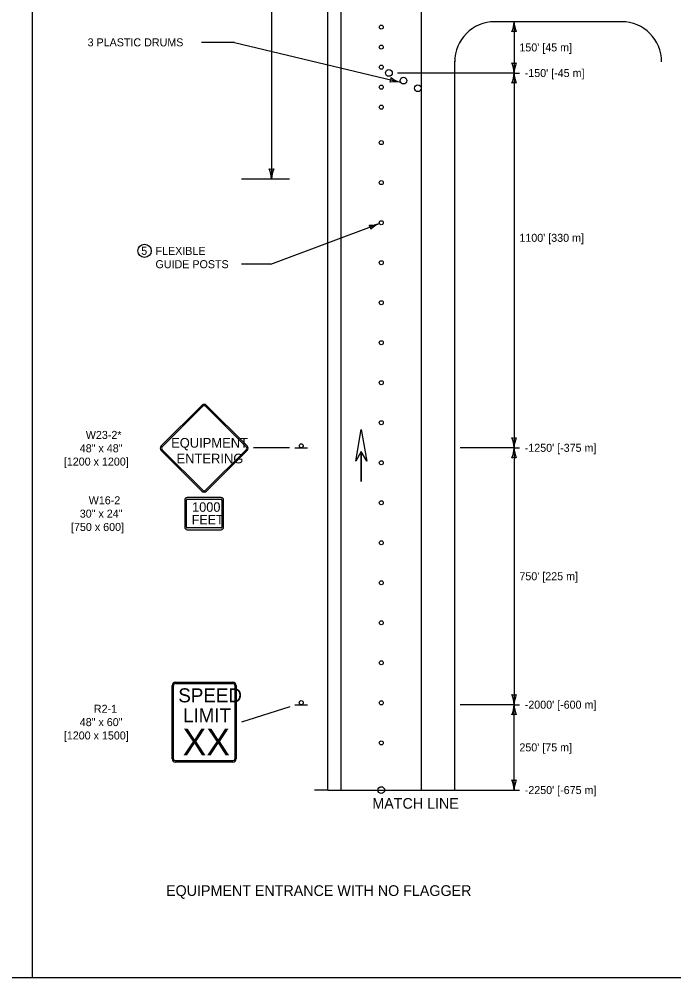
# Model space of a CAD drawing. Extents: x 49991.4 to 50021, y 49987.6 to 50011.4.
# Drawn here: x 50004.19 to 50009.09, y 49987.8 to 49994.99 of the extents above; entities that cross this region are included whole.
import ezdxf

# ---------------------------------------------------------------- set-up
doc = ezdxf.new("R2010")
doc.units = 0
for name, color, linetype in [('Level 1', 7, 'Continuous'), ('Level 2', 7, 'Continuous'), ('Level 3', 7, 'Continuous'), ('Level 6', 7, 'Continuous')]:
    doc.layers.add(name, color=color, linetype=linetype)

msp = doc.modelspace()

# ---------------------------------------------------------------- linework, layer by layer
at = {"layer": 'Level 1'}
for p, q in [((50006.5002, 49989.2066), (50006.5002, 49998.1941)), ((50006.6002, 49989.2066), (50006.6002, 49998.1941)), ((50007.2002, 49989.2066), (50007.2002, 49998.1941)), ((50008.7008, 49994.9668), (50007.7502, 49994.9668)), ((50007.4502, 49989.2066), (50007.4502, 49994.6713)), ((50005.251, 49991.787), (50005.5551, 49992.091)), ((50005.2581, 49991.7799), (50005.5621, 49992.084)), ((50005.5834, 49992.084), (50005.8874, 49991.7799)), ((50005.5904, 49992.091), (50005.8945, 49991.787)), ((50005.5621, 49991.4546), (50005.2581, 49991.7587)), ((50005.8874, 49991.7587), (50005.5834, 49991.4546)), ((50006.2519, 49991.7726), (50006.3479, 49991.7726)), ((50005.5551, 49991.4476), (50005.251, 49991.7516)), ((50005.8945, 49991.7516), (50005.5904, 49991.4476)), ((50006.7502, 49991.5199), (50006.7502, 49991.7458)), ((50006.7505, 49991.5199), (50006.7505, 49991.7458)), ((50005.7001, 49991.4002), (50005.4453, 49991.4002)), ((50005.4271, 49991.38), (50005.4271, 49991.1784)), ((50005.4393, 49991.1784), (50005.4393, 49991.38)), ((50005.4453, 49991.3868), (50005.7001, 49991.3868)), ((50005.7061, 49991.38), (50005.7061, 49991.1784)), ((50005.7183, 49991.1784), (50005.7183, 49991.38)), ((50005.7001, 49991.1717), (50005.4453, 49991.1717)), ((50005.4453, 49991.1583), (50005.7001, 49991.1583)), ((50005.3327, 49989.4409), (50005.3327, 49989.9909)), ((50005.3427, 49989.4409), (50005.3427, 49989.9909)), ((50005.3577, 49990.0159), (50005.7877, 49990.0159)), ((50005.3577, 49990.0059), (50005.7877, 49990.0059)), ((50005.8027, 49989.9909), (50005.8027, 49989.4409)), ((50005.8127, 49989.9909), (50005.8127, 49989.4409)), ((50006.252, 49989.8466), (50006.348, 49989.8466)), ((50005.7877, 49989.4259), (50005.3577, 49989.4259)), ((50005.7877, 49989.4159), (50005.3577, 49989.4159))]:
    msp.add_line(p, q, dxfattribs=at)
for points in [[(49999.3835, 49998.9992), (50016.7501, 49998.9992), (50016.7501, 49987.7988), (49999.3835, 49987.7988)], [(50006.7085, 49991.6735), (50006.7502, 49991.91), (50006.7921, 49991.6735), (50006.7502, 49991.7457)]]:
    msp.add_lwpolyline(points, close=True, dxfattribs=at)
for centre, radius in [((50006.9002, 49994.9266), 0.015), ((50006.9002, 49994.7766), 0.015), ((50006.9002, 49994.6266), 0.015), ((50006.9575, 49994.583), 0.025), ((50006.9002, 49994.4766), 0.015), ((50007.0658, 49994.5256), 0.025), ((50007.174, 49994.4683), 0.025), ((50006.9002, 49994.3266), 0.015), ((50006.9002, 49994.3266), 0.015), ((50006.9002, 49994.0606), 0.015), ((50006.9002, 49993.7606), 0.015), ((50006.9002, 49993.4606), 0.015), ((50006.9002, 49993.1606), 0.015), ((50006.9002, 49992.8606), 0.015), ((50006.9002, 49992.5606), 0.015), ((50006.9002, 49992.2606), 0.015), ((50006.9002, 49991.9606), 0.015), ((50006.2999, 49991.7878), 0.0152), ((50006.9002, 49991.6606), 0.015), ((50006.9002, 49991.3606), 0.015), ((50006.9002, 49991.0606), 0.015), ((50006.9002, 49990.7606), 0.015), ((50006.9002, 49990.4606), 0.015), ((50006.9002, 49990.1606), 0.015), ((50006.9002, 49990.1606), 0.015), ((50006.3, 49989.8618), 0.0152), ((50006.9002, 49989.8606), 0.015), ((50006.9002, 49989.5606), 0.015), ((50006.9001, 49989.2066), 0.025)]:
    msp.add_circle(centre, radius, dxfattribs=at)
for centre, radius, start, end in [((50007.7502, 49994.6668), 0.3, 90, 180), ((50008.7008, 49994.6668), 0.3, 0, 90), ((50005.5727, 49992.0733), 0.025, 45, 135), ((50005.5727, 49992.0733), 0.015, 45, 135), ((50005.2686, 49991.7693), 0.025, 134.99976, 225), ((50005.2686, 49991.7693), 0.015, 134.99976, 225), ((50005.8768, 49991.7693), 0.015, 315, 45), ((50005.8768, 49991.7693), 0.025, 315, 45), ((50005.5727, 49991.4652), 0.025, 225.00043, 315), ((50005.5727, 49991.4652), 0.015, 225.00043, 315), ((50005.3577, 49989.991), 0.025, 90, 180), ((50005.3577, 49989.991), 0.015, 90, 180), ((50005.7877, 49989.991), 0.025, 0, 90), ((50005.7877, 49989.991), 0.015, 0, 90), ((50005.3577, 49989.441), 0.025, 180, 270), ((50005.3577, 49989.441), 0.015, 180, 270), ((50005.7877, 49989.441), 0.025, 270, 0), ((50005.7877, 49989.441), 0.015, 270, 0)]:
    msp.add_arc(centre, radius, start, end, dxfattribs=at)
for centre, major_axis, start_param, end_param in [((50005.4453, 49991.38), (0, 0.0202), 0, 1.570796), ((50005.7001, 49991.38), (0, 0.0202), 4.712389, 6.283185), ((50005.4453, 49991.38), (0, 0.00672), 0, 1.570796), ((50005.7001, 49991.38), (0, 0.00672), 4.712389, 6.283185), ((50005.4453, 49991.1784), (0, -0.0202), 4.712389, 6.283185), ((50005.4453, 49991.1784), (0, -0.00672), 4.712389, 6.283185), ((50005.7001, 49991.1784), (0, -0.00672), 0, 1.570796), ((50005.7001, 49991.1784), (0, -0.0202), 0, 1.570796)]:
    msp.add_ellipse(centre, major_axis=major_axis, ratio=0.9025, start_param=start_param, end_param=end_param, dxfattribs=at)
at = {"layer": 'Level 2'}
msp.add_circle((50005.126, 49993.2496), 0.05, dxfattribs=at)
at = {"layer": 'Level 3'}
for p, q in [((50004.2835, 49998.9992), (50004.2835, 49987.7988)), ((50006.0772, 49996.2068), (50006.0772, 49993.7873)), ((50007.895, 49994.9668), (50007.895, 49994.5826)), ((50005.8, 49994.8126), (50005.553, 49994.8126)), ((50005.8, 49994.8126), (50007.0437, 49994.5138)), ((50007.895, 49994.5826), (50007.0225, 49994.5826)), ((50007.895, 49994.5826), (50007.935, 49994.5826)), ((50007.895, 49994.5826), (50007.895, 49993.7873)), ((50006.212, 49993.7873), (50005.8527, 49993.7873)), ((50007.895, 49993.7873), (50007.895, 49991.7726)), ((50006.0733, 49993.1494), (50006.8864, 49993.4548)), ((50006.0733, 49993.1494), (50005.8527, 49993.1494)), ((50006.2119, 49991.7726), (50005.9418, 49991.7726)), ((50007.895, 49991.7726), (50007.4902, 49991.7726)), ((50007.895, 49991.7726), (50007.935, 49991.7726)), ((50007.895, 49991.7726), (50007.895, 49989.8466)), ((50006.215, 49989.8314), (50005.8527, 49989.7159)), ((50007.895, 49989.8466), (50007.4902, 49989.8466)), ((50007.895, 49989.2066), (50007.895, 49989.8466)), ((50007.895, 49989.8466), (50007.935, 49989.8466))]:
    msp.add_line(p, q, dxfattribs=at)
for centre, radius, start, end in [((50007.6728, 49994.976), 0.2223, 337.45601, 357.63952), ((50008.1277, 49994.9783), 0.233, 182.82731, 202.07716), ((50007.895, 49994.8386), 0.0548, 72.13882, 107.86118), ((50007.895, 49994.7108), 0.0548, 252.13882, 287.86118), ((50007.6623, 49994.5711), 0.233, 2.82731, 22.07716), ((50008.1171, 49994.5734), 0.2223, 157.45601, 177.63952), ((50007.6623, 49994.5941), 0.233, 337.92284, 357.17269), ((50008.1171, 49994.5917), 0.2223, 182.36048, 202.54399), ((50006.9191, 49994.5438), 0.0548, 328.62967, 4.35204), ((50007.0005, 49994.2848), 0.233, 79.31817, 98.56802), ((50007.1045, 49994.7277), 0.2223, 233.94687, 254.13037), ((50007.895, 49994.4544), 0.0548, 72.13882, 107.86118), ((50006.0772, 49993.9155), 0.0548, 252.13882, 287.86118), ((50005.8445, 49993.7758), 0.233, 2.82731, 22.07716), ((50006.2993, 49993.7781), 0.2223, 157.45601, 177.63952), ((50006.813, 49993.6647), 0.2223, 269.09342, 289.27693), ((50006.7672, 49993.4076), 0.0548, 3.77623, 39.49859), ((50006.9829, 49993.2428), 0.233, 114.46472, 133.71457), ((50007.6728, 49991.7634), 0.2223, 2.36048, 22.54399), ((50007.895, 49991.9008), 0.0548, 252.13882, 287.86118), ((50008.1277, 49991.7611), 0.233, 157.92284, 177.17269), ((50007.6728, 49991.7817), 0.2223, 337.45601, 357.63952), ((50008.1277, 49991.7841), 0.233, 182.82731, 202.07716), ((50007.895, 49991.6444), 0.0548, 72.13882, 107.86118), ((50007.895, 49989.9748), 0.0548, 252.13882, 287.86118), ((50007.6623, 49989.8351), 0.233, 2.82731, 22.07716), ((50008.1171, 49989.8374), 0.2223, 157.45601, 177.63952), ((50007.6728, 49989.8557), 0.2223, 337.45601, 357.63952), ((50008.1277, 49989.8581), 0.233, 182.82731, 202.07716), ((50007.895, 49989.7184), 0.0548, 72.13882, 107.86118), ((50007.895, 49989.3348), 0.0548, 252.13882, 287.86118), ((50007.6623, 49989.1951), 0.233, 2.82731, 22.07716), ((50008.1171, 49989.1974), 0.2223, 157.45601, 177.63952)]:
    msp.add_arc(centre, radius, start, end, dxfattribs=at)
at = {"layer": 'Level 6'}
for p, q in [((50006.5002, 49989.2066), (50006.4002, 49989.2066)), ((50006.5002, 49989.2066), (50007.895, 49989.2066)), ((50007.895, 49989.2066), (50007.935, 49989.2066))]:
    msp.add_line(p, q, dxfattribs=at)

# ---------------------------------------------------------------- texts
at = {"layer": 'Level 1'}
for s, height, p in [('EQUIPMENT', 0.0725, (50005.3249, 49991.7735)), ('ENTERING', 0.0725, (50005.3656, 49991.656)), ('1000', 0.07124, (50005.4824, 49991.2927)), ('FEET', 0.06989, (50005.4795, 49991.1986)), ('SPEED', 0.10512, (50005.3789, 49989.8643)), ('LIMIT', 0.10512, (50005.4143, 49989.7142)), ('XX', 0.19892, (50005.4111, 49989.4669))]:
    msp.add_text(s, height=height, dxfattribs=at).set_placement(p)
at = {"layer": 'Level 2'}
for s, height, p in [('3 PLASTIC DRUMS', 0.06, (50004.6992, 49994.7826)), ("150' [45 m]", 0.06, (50007.935, 49994.7446)), ("-150' [-45 m]", 0.06, (50007.975, 49994.5526)), ("1100' [330 m]", 0.06, (50007.935, 49993.3171)), ('5', 0.06, (50005.1011, 49993.2196)), ('FLEXIBLE', 0.06, (50005.2081, 49993.2194)), ('GUIDE POSTS', 0.06, (50005.2081, 49993.1194)), ('W23-2*', 0.06, (50004.6857, 49991.8393)), ('48" x 48"', 0.06, (50004.6405, 49991.7393)), ("-1250' [-375 m]", 0.06, (50007.975, 49991.7426)), ('[1200 x 1200]', 0.06, (50004.5211, 49991.6393)), ('W16-2', 0.06, (50004.7074, 49991.3492)), ('30" x 24"', 0.06, (50004.6405, 49991.2492)), ('[750 x 600]', 0.06, (50004.5749, 49991.1492)), ("750' [225 m]", 0.06, (50007.935, 49990.7796)), ('R2-1', 0.06, (50004.7461, 49989.7859)), ("-2000' [-600 m]", 0.06, (50007.975, 49989.8166)), ('48" x 60"', 0.06, (50004.6405, 49989.6859)), ('[1200 x 1500]', 0.06, (50004.5211, 49989.5859)), ("250' [75 m]", 0.06, (50007.935, 49989.4966)), ("-2250' [-675 m]", 0.06, (50007.975, 49989.1766)), ('MATCH LINE', 0.08, (50006.833, 49989.0666)), ('EQUIPMENT ENTRANCE WITH NO FLAGGER', 0.08, (50005.2871, 49988.4127))]:
    msp.add_text(s, height=height, dxfattribs=at).set_placement(p)

doc.saveas('drawing.dxf')
